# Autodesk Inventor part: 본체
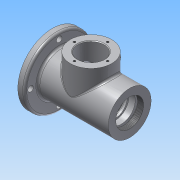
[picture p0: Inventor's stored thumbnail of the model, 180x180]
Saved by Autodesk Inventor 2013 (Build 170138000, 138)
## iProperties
Created: 2016-08
Part Number: 본체
Material: 알루미늄 6061
Document SubType Name: Modeling
Designer: Administrator
Density: 2.71 g/cm^3
Mass: 730.774 g
Surface Area: 616.448 cm^2
Volume: 269.658 cm^3
Author: Administrator
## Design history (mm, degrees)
sketch "스케치1"
  geometry: L1 (0, 0)-(115, 0); L2 (115, 0)-(115, 31); L3 (115, 31)-(112, 31); L4 (112, 31)-(112, 50); L5 (112, 50)-(105, 50); L6 (102, 47)-(102, 31); L7 (102, 31)-(0, 31); L8 (0, 31)-(0, 0); L9 (0, 21)-(9, 21); L10 (9, 21)-(9, 24); L11 (9, 24)-(12, 24); L12 (12, 24)-(12, 20); L13 (12, 20)-(21, 20); L14 (21, 20)-(21, 17.5); L15 (21, 17.5)-(24.25, 17.5); L16 (24.25, 17.5)-(24.25, 18.5); L17 (24.25, 18.5)-(26, 18.5); L18 (26, 18.5)-(26, 17.5); L19 (26, 17.5)-(36, 17.5); L20 (37, 18.5)-(37, 23); L21 (40, 26)-(72, 26); L22 (75, 23)-(75, 18.5); L23 (76, 17.5)-(85.7, 17.5); L24 (86, 17.2)-(86, 16.5); L25 (86, 16.5)-(88, 16.5); L26 (91, 13.5)-(91, 10); L27 (91, 10)-(93.7, 10); L28 (93.7, 10)-(93.7, 12.2); L29 (94, 12.5)-(100.3, 12.5); L30 (115, 0)-(115, 21); L31 (101, 12.5)-(100.3, 12.5); L32 (101, 12.5)-(101, 12.904); L33 (101, 16)-(103.089, 16); L34 (102.991, 16.711)-(115, 21); L35 (100.3, 12.5)-(101, 12.904); L36 (100.3, 12.5)-(101, 12.5); L37 (101, 12.904)-(101, 13.886); L38 (36, 17.5)-(37, 18.5); L39 (75, 18.5)-(76, 17.5); L40 (9, 21)-(9, 0); A1 r 0.3 centre (94, 12.2) between (94, 12.5) and (93.7, 12.2); A2 r 0.3 centre (85.7, 17.2) between (86, 17.2) and (85.7, 17.5); A3 r 3 centre (104, 13.886) between (102.991, 16.711) and (101, 13.886); A4 r 3 centre (72, 23) between (75, 23) and (72, 26); A5 r 3 centre (40, 23) between (40, 26) and (37, 23); A6 r 3 centre (88, 13.5) between (91, 13.5) and (88, 16.5); A7 r 3 centre (105, 47) between (105, 50) and (102, 47); 8 further points
  constraints: 80 end point, 21 point on line, 18 perpendicular, 16 tangent, 15 parallel, 14 point on circle, 7 centre point, 3 equal radius, 1 collinear, 1 horizontal
  dimensions: "d0" = 115 distance of L1.start L1.end; "d1" = 3 distance of L2.end L3.end; "d2" = 10 distance of L4.end point (102, 50); "d3" = 62 diameter of L7 L1; "d4" = 100 diameter of L5 L1; "d5" = 62 diameter of L3 L1; "d6" = 9 distance of L9.start L9.end; "d7" = 3 distance of L10.end L11.end; "d8" = 9 distance of L12.end L13.end; "d9" = 3.25 distance of L14.end L15.end; "d10" = 1.75 distance of L16.end L17.end; "d11" = 11 distance of L18.end point (37, 17.5); "d12" = 38 distance of point (37, 26) point (75, 26); "d13" = 11 distance of point (75, 17.5) point (86, 17.5); "d14" = 5 distance of L24.end point (91, 16.5); "d15" = 2.7 distance of L26.end L27.end; "d16" = 7.3 distance of point (93.7, 12.5) L31.start; "d18" = 42 diameter of L9 L1; "d19" = 48 diameter of L11 L1; "d20" = 40 diameter of L13 L1; "d21" = 35 diameter of L15 L1; "d22" = 37 diameter of L17 L1; "d23" = 35 diameter of L19 L1; "d24" = 52 diameter of L21 L1; "d25" = 35 diameter of L23 L1; "d26" = 33 diameter of L25 L1; "d27" = 20 diameter of L27 L1; "d28" = 25 diameter of L29 L1; "d29" = 21 distance of L1.end L30.end; "d30" = 0.3 radius of A1; "d31" = 0.7 distance of L31.start L29.end; "d32" = 32 diameter of L33 L1; "d33" = 3 radius of A3; "d34" = 3 radius of A4; "d35" = 30 deg angle of L31 L35; "d36" = 3 radius of A7; "d37" = 1 distance of L19.end point (37, 17.5); "d38" = 1 distance of L20.start point (37, 17.5) (= d37); "d39" = 1 distance of L22.end point (75, 17.5) (= d37); "d40" = 1 distance of L23.start point (75, 17.5) (= d39)
revolve "회전1" sketch "스케치1" stored, may be unused: angle "d41" = 90 deg
sketch "스케치2"
  geometry: C1 r 31 at (0, 0) reference; 1 further point
  constraints: 1 coincident
hole "구멍1" sketch "스케치2" at (0, 0) diameter "d42" = 40.376; stored, may be unused: countersink angle "d46" = 90 deg, drill point angle "d48" = 0 deg; dims "d43" = 9, "d44" = 4, "d45" = 2, "d47" = 9
sketch "스케치3"
  geometry: L1 (0, 0)-(-41.5, 0); C1 r 50 at (0, 0) reference; 1 further point
  constraints: 2 end point, 1 coincident, 1 horizontal
  dimensions: "d49" = 41.5 distance of L1.start L1.end
hole "구멍2" sketch "스케치3" at (-41.5, 0) diameter "d50" = 8; stored, may be unused: countersink angle "d54" = 90 deg, drill point angle "d56" = 0 deg; dims "d51" = 9, "d52" = 4, "d53" = 2, "d55" = 9
node "작업 평면1"
sketch "스케치4"
  geometry: L1 (0, -31)-(0, 31) reference; L2 (0, 0)-(56, 0); C1 r 30 at (56, 0)
  constraints: 2 end point, 1 centre point, 1 coincident, 1 perpendicular
  dimensions: "d61" = 56 distance of L2.start L2.end; "d62" = 60 diameter of C1
extrude "돌출1" join sketch "스케치4" stored distance "d63" = 10; taper "d64" = 0 deg
sketch "스케치5"
  geometry: C1 r 30 at (0, 0) reference; C2 r 19 at (0, 0); 1 further point
  constraints: 1 centre point, 1 coincident
  dimensions: "d65" = 38 diameter of C2
extrude "돌출2" cut sketch "스케치5" stored distance "d66" = 10; taper "d67" = 0 deg
sketch "스케치6"
  geometry: L1 (0, 0)-(24, 0); C1 r 30 at (0, 0) reference; 2 further points
  constraints: 2 end point, 1 coincident, 1 horizontal
  dimensions: "d68" = 24 distance of L1.start L1.end
hole "구멍3" sketch "스케치6" at (24, 0) diameter "d69" = 3.242; stored, may be unused: countersink angle "d73" = 90 deg, drill point angle "d75" = 118 deg; dims "d70" = 8, "d71" = 4, "d72" = 2, "d74" = 10
node "작업 평면2"
sketch "스케치7"
  geometry: L1 (30, 0)-(-30, 0) reference; L2 (0, 0)-(0, -10); 2 further points
  constraints: 2 end point, 1 coincident, 1 midpoint, 1 perpendicular, 1 other
  dimensions: "d79" = 10 distance of L2.start L2.end
feature "엠보싱1" sketch "스케치7" dims "d80" = 0.5, "d81" = 0
fillet "모깎기1" dims "d82" = 3
chamfer "모따기1" distance "d85" = 1; stored, may be unused: second distance "d86" = 2, angle "d87" = 45 deg
node "솔리드1"
pattern_circular "원형 패턴1" dims angle "d58" = 360 deg
pattern_circular "원형 패턴2" dims angle "d77" = 360 deg
mirror "대칭1"
other parameters: "d60" = 49
